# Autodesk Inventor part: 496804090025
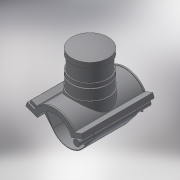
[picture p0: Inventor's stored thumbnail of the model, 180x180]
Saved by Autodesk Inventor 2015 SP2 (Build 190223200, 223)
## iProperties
Created: 2017-07
Part Number: 496804090025
Material: Generic
Description: PLASSON BALLOON SADDLE 90-2.1/2"
Document SubType Name: Modeling
Designer: KIM
Density: 1 g/cm^3
Appearance: Default
Author: KIM
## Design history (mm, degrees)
derived "496804.ipt"
feature "Solid1::496804.ipt"
feature "Solid2::496804.ipt"
tag "TaggingFeature1"
body "Solid1"
body "Solid2"
other parameters: "d1" = 112.5, "d4" = 176, "d5" = 0, "d40" = 58.5, "d96" = 114.75, "d97" = 3.52, "d98" = 0, "d120" = 140 deg, "d121" = 24.228, "d122" = 20 deg, "d123" = 225, "d124" = 67.5, "d126" = 0, "d143" = 92.7, "d145" = 17.30769, "d149" = 1.35, "d150" = 19.03846, "d153" = 176, "d154" = 0, "d159" = 4.5, "d161" = 1.35, "d162" = 105.6, "d163" = 0, "d164" = 45, "d168" = 59.21053, "d170" = 1.35, "d172" = 0, "d173" = 1, "d175" = 45, "d176" = 20 deg, "d177" = 10.8, "d180" = 0, "d185" = 57.2, "d186" = 57.2, "d187" = 56.25, "d188" = 6.75, "d190" = 0, "d193" = 4.5, "d194" = 4.4, "d195" = 90 deg, "d197" = 0, "d199" = 0, "d200" = 105, "d201" = 1, "d203" = 94.5, "d204" = 97.65, "d205" = 85.5, "d206" = 1.8, "d207" = 52.5, "d208" = 42, "d209" = 84, "d210" = 15.75, "d214" = 112.5, "d216" = 0, "d217" = 71, "d219" = 4.5, "d220" = 15.98, "d221" = 8 deg, "d223" = 15.36581, "d224" = 7.6829, "d226" = 0, "d227" = -17.6, "d228" = 2.25, "d229" = 19.8, "B_" = 142, "H_" = 105, "L_" = 176, "d_t" = 6, "d148" = 1.35, "d160" = 1.35, "d169" = 1.35, "d192" = 4.5, "d222" = 19.20726
